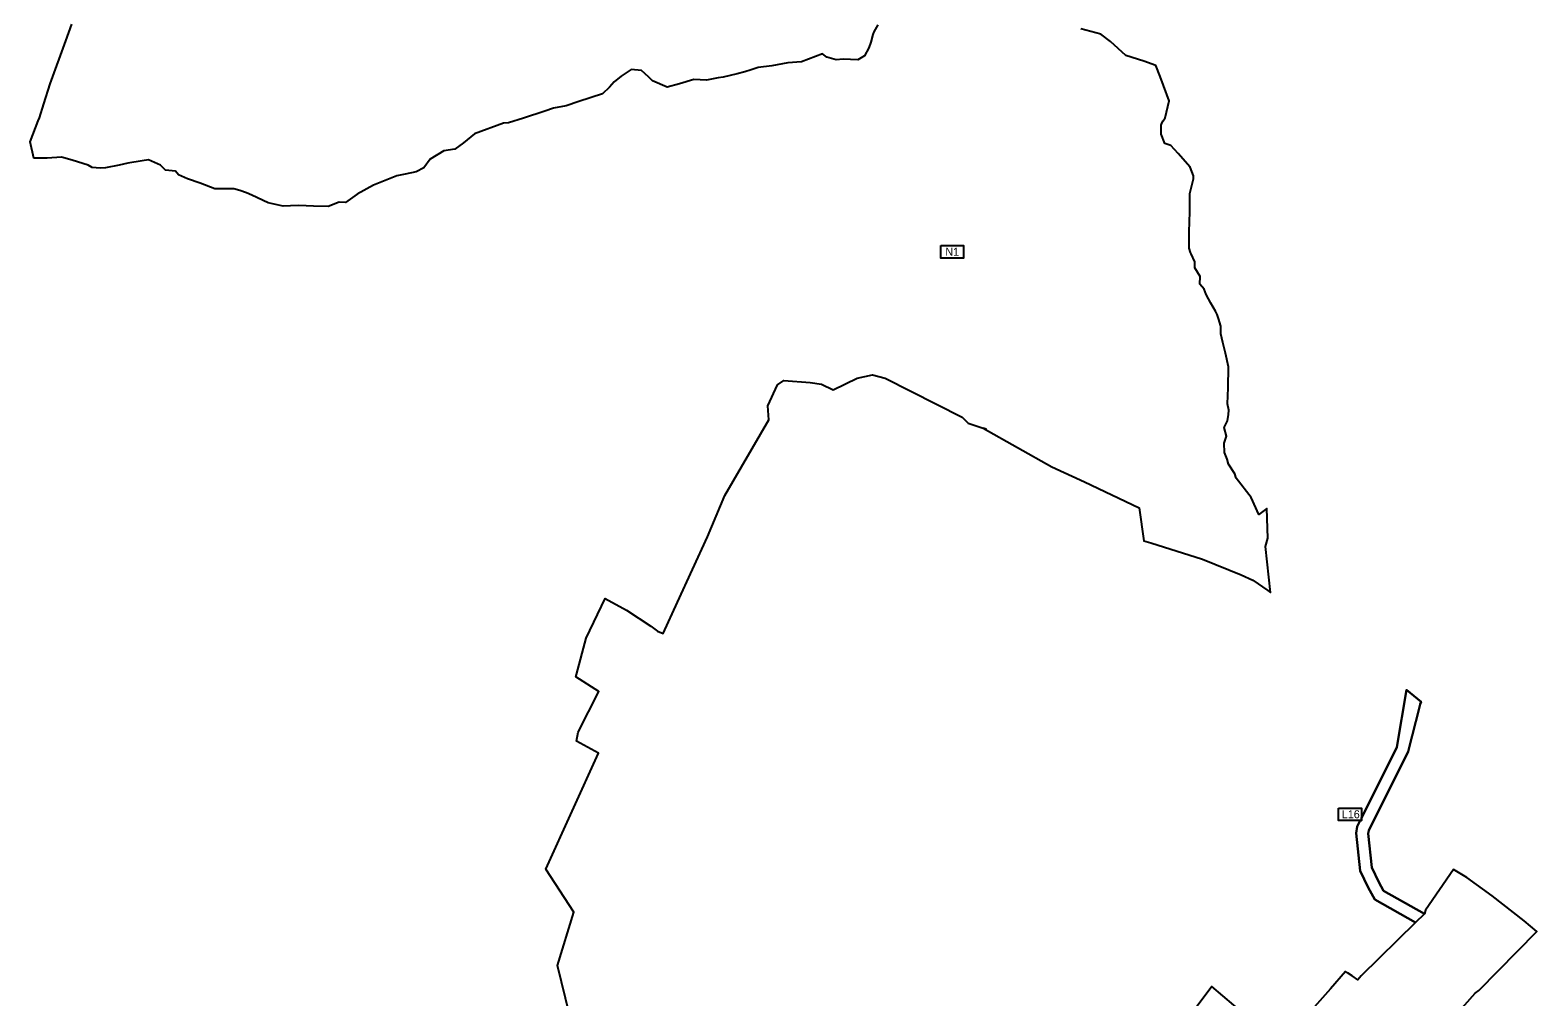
# Model space of a CAD drawing. Extents: x -547623 to -530360, y -1095798 to -1086523.
# Drawn here: x -543866 to -541983, y -1091356 to -1090148 of the extents above; entities that cross this region are included whole.
import ezdxf

# ---------------------------------------------------------------- set-up
doc = ezdxf.new("R2010")
doc.units = 0
for name, color, linetype in [('Vrstva 27', 7, 'Continuous'), ('Vrstva 33', 7, 'Continuous'), ('Vrstva 36', 7, 'Continuous'), ('Vrstva 73', 7, 'Continuous')]:
    doc.layers.add(name, color=color, linetype=linetype)

msp = doc.modelspace()

# ---------------------------------------------------------------- linework, layer by layer
at = {"layer": 'Vrstva 27'}
for points in [[(-542806.2, -1090140.9), (-542811, -1090149.5), (-542812.2, -1090152.9), (-542814.7, -1090162.8), (-542817.4, -1090169.8), (-542823, -1090179.9), (-542831.1, -1090184.7), (-542849.4, -1090183.7), (-542858.4, -1090184.7), (-542869.8, -1090181.2), (-542875.4, -1090177.4), (-542901.7, -1090187.4), (-542918.8, -1090188.4), (-542938.4, -1090192.3), (-542955.5, -1090194.2), (-542964.3, -1090197.2), (-542972.5, -1090199.7), (-542981.8, -1090202.3), (-542999.5, -1090206.3), (-543005.7, -1090207.4), (-543020.1, -1090210), (-543036.1, -1090209.4), (-543054, -1090214.5), (-543069.4, -1090218.8), (-543087.7, -1090210.8), (-543092.9, -1090205.8), (-543101.6, -1090198.2), (-543114.5, -1090196.9), (-543127.1, -1090205.1), (-543135.6, -1090212.4), (-543141.3, -1090219), (-543150.2, -1090227.2), (-543180, -1090236.7), (-543195.8, -1090242.2), (-543211.6, -1090245.3), (-543222.4, -1090248.7), (-543249, -1090257.4), (-543267.5, -1090263.5), (-543274.1, -1090263.7), (-543310, -1090277.2), (-543324.1, -1090288.3), (-543334.8, -1090296.2), (-543348.6, -1090298.5), (-543365.7, -1090308.8), (-543373.7, -1090319.5), (-543383.2, -1090324.7), (-543396.8, -1090327.6), (-543407.1, -1090329.8), (-543436.2, -1090341.3), (-543456.7, -1090352.7), (-543471.3, -1090363.1), (-543479.2, -1090362.6), (-543493.1, -1090368.1), (-543511.4, -1090367.5), (-543529.8, -1090366.7), (-543540, -1090367.3), (-543549.1, -1090367.7), (-543568, -1090363.5), (-543588.3, -1090354), (-543595.2, -1090350.8), (-543603.5, -1090348), (-543611, -1090345.9), (-543634.8, -1090346.1), (-543653, -1090338.7), (-543669, -1090333.4), (-543680, -1090328.6), (-543684, -1090324), (-543696.2, -1090322.6), (-543702.6, -1090316.4), (-543717.8, -1090309.8), (-543725.6, -1090310.8), (-543743.4, -1090313.7), (-543754.2, -1090316.2), (-543771.5, -1090319.6), (-543778.2, -1090320.3), (-543788, -1090319.4), (-543793, -1090316.5), (-543812.9, -1090310.2), (-543826.4, -1090306.3), (-543844.2, -1090307.4), (-543860.8, -1090307.4), (-543865.5, -1090287.1), (-543855.3, -1090261.1), (-543854, -1090257.1), (-543848.6, -1090239.8), (-543840.3, -1090214.6), (-543820.9, -1090161.1), (-543813.6, -1090140.2)], [(-542330, -1090753.1), (-542339.5, -1090731.6), (-542358.4, -1090707.5), (-542359.9, -1090702.1), (-542368, -1090690.2), (-542369.6, -1090683.6), (-542372.8, -1090675.5), (-542373.2, -1090663.6), (-542370.5, -1090655), (-542373.2, -1090644.1), (-542369.3, -1090636), (-542368, -1090628.1), (-542367.4, -1090622.4), (-542369.1, -1090614.8), (-542368.5, -1090594.5), (-542367.8, -1090568.4), (-542371.8, -1090551.4), (-542375, -1090538.1), (-542377.6, -1090527), (-542377.6, -1090517.7), (-542380.4, -1090507.8), (-542381.9, -1090503), (-542384.1, -1090499), (-542390.1, -1090488.8), (-542396, -1090477.8), (-542398.2, -1090471.5), (-542403.9, -1090465.1), (-542403.2, -1090455.5), (-542410.1, -1090444.7), (-542410.1, -1090437.1), (-542414.7, -1090427.3), (-542415.4, -1090425.6), (-542417.2, -1090420.1), (-542416.9, -1090399.8), (-542416.3, -1090374.6), (-542416.1, -1090351.7), (-542411.8, -1090333.5), (-542411.6, -1090329.8), (-542415.8, -1090318.7), (-542430.8, -1090301.9), (-542439.8, -1090291.6), (-542447.3, -1090289.2), (-542452.2, -1090277.8), (-542452, -1090266.3), (-542451.1, -1090263.9), (-542449.4, -1090261), (-542446.9, -1090257), (-542442.1, -1090235.8), (-542449.2, -1090216.6), (-542453.4, -1090205.5), (-542458.8, -1090191.6), (-542473.6, -1090186.5), (-542496.2, -1090179.2), (-542515.5, -1090161.8), (-542527.3, -1090152.8), (-542552.3, -1090146.1)], [(-543191.3, -1091378), (-543206.6, -1091316.7), (-543185.9, -1091250), (-543220.9, -1091196.4), (-543155.3, -1091051.1), (-543182.7, -1091036.3), (-543180.5, -1091024.9), (-543154.8, -1090974.3), (-543183.4, -1090955.8), (-543182.6, -1090952.7), (-543170.7, -1090907.4), (-543146.7, -1090857.8), (-543120.3, -1090872.7), (-543089.7, -1090892.7), (-543081.6, -1090898.6), (-543074.3, -1090901.8), (-543056.3, -1090862.5), (-543018.8, -1090780.9), (-542997.3, -1090729.3), (-542942.4, -1090634.5), (-542943.8, -1090617.1), (-542931.7, -1090590.7), (-542923.6, -1090585.5), (-542890.8, -1090588.1), (-542876.6, -1090590), (-542861.9, -1090597.3), (-542832.1, -1090582.7), (-542812.8, -1090578.3), (-542796.8, -1090582.4), (-542700.9, -1090631.2), (-542693.2, -1090638.7), (-542674.6, -1090645), (-542670.9, -1090646.3), (-542674.6, -1090645), (-542588.8, -1090693.4), (-542547.8, -1090712.1), (-542479.5, -1090744.8)], [(-542479.5, -1090744.8), (-542473.9, -1090785.7)], [(-542321.7, -1090793), (-542318.9, -1090782.4), (-542320, -1090745.4), (-542330, -1090753.1)], [(-542473.9, -1090785.7), (-542464.9, -1090788.5)], [(-542464.9, -1090788.5), (-542400.3, -1090808.8), (-542352.2, -1090828.5), (-542337.4, -1090835), (-542318.8, -1090848), (-542315.2, -1090850.3)], [(-542315.2, -1090850.3), (-542321.7, -1090793)], [(-542107.9, -1091405.8), (-542059.8, -1091351.1), (-542055.2, -1091347.9), (-541982.5, -1091274.2), (-541998.5, -1091260.7), (-542038.5, -1091229.7), (-542069.9, -1091206.5), (-542086.6, -1091196.6), (-542121.6, -1091247.6), (-542123.1, -1091252.1), (-542134.2, -1091263), (-542202.1, -1091329.4), (-542206.4, -1091334.4), (-542213.4, -1091329.7), (-542219.1, -1091325.8), (-542221.5, -1091324.1), (-542240.4, -1091345.9), (-542290.6, -1091402)], [(-542347.4, -1091377.7), (-542388.6, -1091342.8), (-542421, -1091385.7)]]:
    msp.add_lwpolyline(points, dxfattribs=at)
at = {"layer": 'Vrstva 33'}
msp.add_lwpolyline([(-542134.2, -1091263), (-542185, -1091234.1), (-542193.4, -1091219.3), (-542203.2, -1091198.4), (-542208.5, -1091151.1), (-542206.9, -1091142.8), (-542203.2, -1091135.4), (-542201.8, -1091135.4), (-542201.8, -1091132.5), (-542157.5, -1091043.8), (-542145.5, -1090972), (-542127.1, -1090987.2), (-542128.3, -1090990.1), (-542128.8, -1090992.1), (-542143.4, -1091049.1), (-542192.6, -1091147.7), (-542193.3, -1091151.6), (-542188.6, -1091194.3), (-542180, -1091212.4), (-542174, -1091223.1), (-542123.1, -1091252.1), (-542134.2, -1091263)], dxfattribs=at)
at = {"layer": 'Vrstva 36'}
for points in [[(-542727.6, -1090416.9), (-542699, -1090416.9), (-542699, -1090432.4), (-542727.6, -1090432.4)], [(-542230.4, -1091119.9), (-542201.8, -1091119.9), (-542201.8, -1091135.4), (-542230.4, -1091135.4)]]:
    msp.add_lwpolyline(points, close=True, dxfattribs=at)
at = {"layer": 'Vrstva 73'}
for points in [[(-542806.2, -1090140.9), (-542811, -1090149.5), (-542812.2, -1090152.9), (-542814.7, -1090162.8), (-542817.4, -1090169.8), (-542823, -1090179.9), (-542831.1, -1090184.7), (-542849.4, -1090183.7), (-542858.4, -1090184.7), (-542869.8, -1090181.2), (-542875.4, -1090177.4), (-542901.7, -1090187.4), (-542918.8, -1090188.4), (-542938.4, -1090192.3), (-542955.5, -1090194.2), (-542964.3, -1090197.2), (-542972.5, -1090199.7), (-542981.8, -1090202.3), (-542999.5, -1090206.3), (-543005.7, -1090207.4), (-543020.1, -1090210), (-543036.1, -1090209.4), (-543054, -1090214.5), (-543069.4, -1090218.8), (-543087.7, -1090210.8), (-543092.9, -1090205.8), (-543101.6, -1090198.2), (-543114.5, -1090196.9), (-543127.1, -1090205.1), (-543135.6, -1090212.4), (-543141.3, -1090219), (-543150.2, -1090227.2), (-543180, -1090236.7), (-543195.8, -1090242.2), (-543211.6, -1090245.3), (-543222.4, -1090248.7), (-543249, -1090257.4), (-543267.5, -1090263.5), (-543274.1, -1090263.7), (-543310, -1090277.2), (-543324.1, -1090288.3), (-543334.8, -1090296.2), (-543348.6, -1090298.5), (-543365.7, -1090308.8), (-543373.7, -1090319.5), (-543383.2, -1090324.7), (-543396.8, -1090327.6), (-543407.1, -1090329.8), (-543436.2, -1090341.3), (-543456.7, -1090352.7), (-543471.3, -1090363.1), (-543479.2, -1090362.6), (-543493.1, -1090368.1), (-543511.4, -1090367.5), (-543529.8, -1090366.7), (-543540, -1090367.3), (-543549.1, -1090367.7), (-543568, -1090363.5), (-543588.3, -1090354), (-543595.2, -1090350.8), (-543603.5, -1090348), (-543611, -1090345.9), (-543634.8, -1090346.1), (-543653, -1090338.7), (-543669, -1090333.4), (-543680, -1090328.6), (-543684, -1090324), (-543696.2, -1090322.6), (-543702.6, -1090316.4), (-543717.8, -1090309.8), (-543725.6, -1090310.8), (-543743.4, -1090313.7), (-543754.2, -1090316.2), (-543771.5, -1090319.6), (-543778.2, -1090320.3), (-543788, -1090319.4), (-543793, -1090316.5), (-543812.9, -1090310.2), (-543826.4, -1090306.3), (-543844.2, -1090307.4), (-543860.8, -1090307.4), (-543865.5, -1090287.1), (-543855.3, -1090261.1), (-543854, -1090257.1), (-543848.6, -1090239.8), (-543840.3, -1090214.6), (-543820.9, -1090161.1), (-543813.6, -1090140.2)], [(-543191.3, -1091378), (-543206.6, -1091316.7), (-543185.9, -1091250), (-543220.9, -1091196.4), (-543155.3, -1091051.1), (-543182.7, -1091036.3), (-543180.5, -1091024.9), (-543154.8, -1090974.3), (-543183.4, -1090955.8), (-543182.6, -1090952.7), (-543170.7, -1090907.4), (-543146.7, -1090857.8), (-543120.3, -1090872.7), (-543089.7, -1090892.7), (-543081.6, -1090898.6), (-543074.3, -1090901.8), (-543056.3, -1090862.5), (-543018.8, -1090780.9), (-542997.3, -1090729.3), (-542942.4, -1090634.5), (-542943.8, -1090617.1), (-542931.7, -1090590.7), (-542923.6, -1090585.5), (-542890.8, -1090588.1), (-542876.6, -1090590), (-542861.9, -1090597.3), (-542832.1, -1090582.7), (-542812.8, -1090578.3), (-542796.8, -1090582.4), (-542700.9, -1090631.2), (-542693.2, -1090638.7), (-542674.6, -1090645), (-542670.9, -1090646.3), (-542674.6, -1090645), (-542588.8, -1090693.4), (-542547.8, -1090712.1), (-542479.5, -1090744.8), (-542473.9, -1090785.7), (-542464.9, -1090788.5), (-542400.3, -1090808.8), (-542352.2, -1090828.5), (-542337.4, -1090835), (-542318.8, -1090848), (-542315.2, -1090850.3), (-542321.7, -1090793), (-542318.9, -1090782.4), (-542320, -1090745.4), (-542330, -1090753.1), (-542339.5, -1090731.6), (-542358.4, -1090707.5), (-542359.9, -1090702.1), (-542368, -1090690.2), (-542369.6, -1090683.6), (-542372.8, -1090675.5), (-542373.2, -1090663.6), (-542370.5, -1090655), (-542373.2, -1090644.1), (-542369.3, -1090636), (-542368, -1090628.1), (-542367.4, -1090622.4), (-542369.1, -1090614.8), (-542368.5, -1090594.5), (-542367.8, -1090568.4), (-542371.8, -1090551.4), (-542375, -1090538.1), (-542377.6, -1090527), (-542377.6, -1090517.7), (-542380.4, -1090507.8), (-542381.9, -1090503), (-542384.1, -1090499), (-542390.1, -1090488.8), (-542396, -1090477.8), (-542398.2, -1090471.5), (-542403.9, -1090465.1), (-542403.2, -1090455.5), (-542410.1, -1090444.7), (-542410.1, -1090437.1), (-542414.7, -1090427.3), (-542415.4, -1090425.6), (-542417.2, -1090420.1), (-542416.9, -1090399.8), (-542416.3, -1090374.6), (-542416.1, -1090351.7), (-542411.8, -1090333.5), (-542411.6, -1090329.8), (-542415.8, -1090318.7), (-542430.8, -1090301.9), (-542439.8, -1090291.6), (-542447.3, -1090289.2), (-542452.2, -1090277.8), (-542452, -1090266.3), (-542451.1, -1090263.9), (-542449.4, -1090261), (-542446.9, -1090257), (-542442.1, -1090235.8), (-542449.2, -1090216.6), (-542453.4, -1090205.5), (-542458.8, -1090191.6), (-542473.6, -1090186.5), (-542496.2, -1090179.2), (-542515.5, -1090161.8), (-542527.3, -1090152.8), (-542552.3, -1090146.1)], [(-542201.8, -1091132.5), (-542201.8, -1091135.4), (-542203.2, -1091135.4), (-542206.9, -1091142.8), (-542208.5, -1091151.1), (-542203.2, -1091198.4), (-542193.4, -1091219.3), (-542185, -1091234.1), (-542134.2, -1091263), (-542123.1, -1091252.1), (-542174, -1091223.1), (-542180, -1091212.4), (-542188.6, -1091194.3), (-542193.3, -1091151.6), (-542192.6, -1091147.7), (-542143.4, -1091049.1), (-542128.8, -1090992.1), (-542128.3, -1090990.1), (-542127.1, -1090987.2), (-542145.5, -1090972), (-542157.5, -1091043.8), (-542201.8, -1091132.5)], [(-542107.9, -1091405.8), (-542059.8, -1091351.1), (-542055.2, -1091347.9), (-541982.5, -1091274.2), (-541998.5, -1091260.7), (-542038.5, -1091229.7), (-542069.9, -1091206.5), (-542086.6, -1091196.6), (-542121.6, -1091247.6), (-542123.1, -1091252.1), (-542134.2, -1091263), (-542202.1, -1091329.4), (-542206.4, -1091334.4), (-542213.4, -1091329.7), (-542219.1, -1091325.8), (-542221.5, -1091324.1), (-542240.4, -1091345.9), (-542290.6, -1091402)], [(-542347.4, -1091377.7), (-542388.6, -1091342.8), (-542421, -1091385.7)]]:
    msp.add_lwpolyline(points, dxfattribs=at)

# ---------------------------------------------------------------- texts
at = {"layer": 'Vrstva 36'}
for s, p in [('N1', (-542721.7, -1090429.6)), ('L16', (-542226.2, -1091132.6))]:
    msp.add_text(s, height=10, dxfattribs=at).set_placement(p)

doc.saveas('drawing.dxf')
